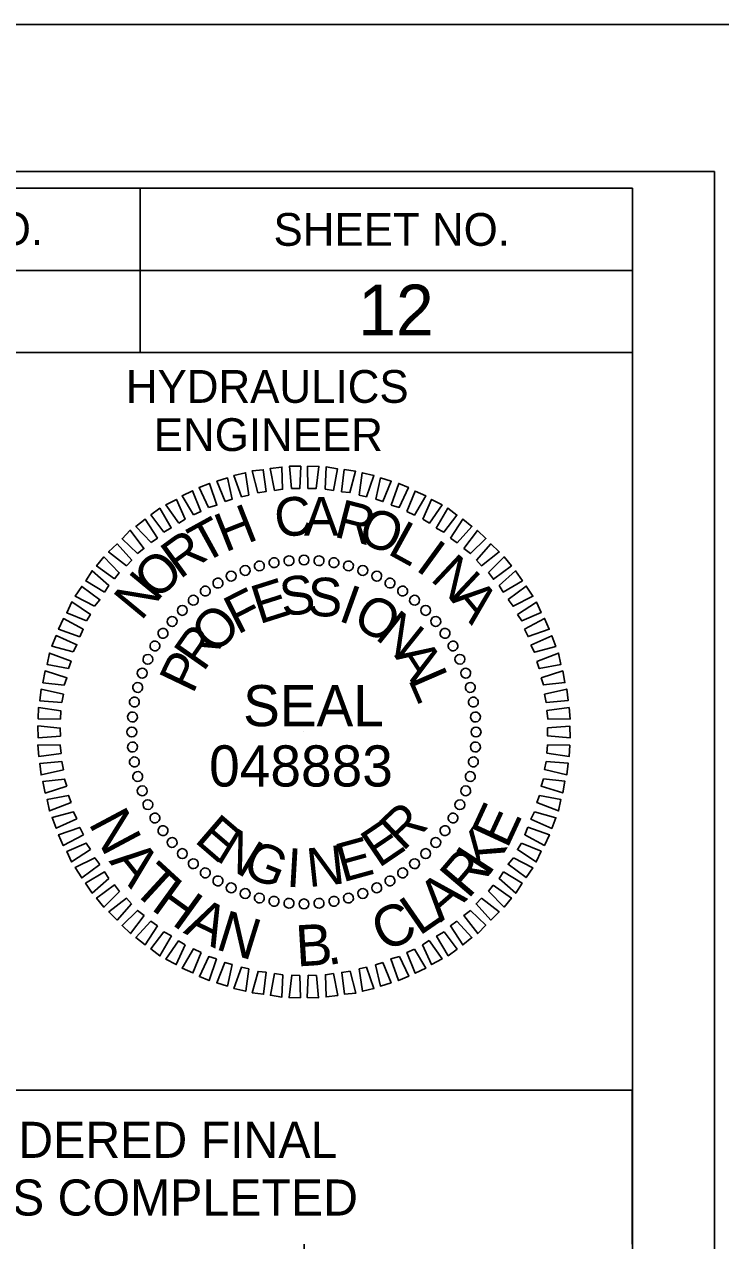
# Model space of a CAD drawing. Extents: x 1650661 to 1652901, y 832691 to 833791.
# Drawn here: x 1652611.6 to 1652717.7, y 833605.5 to 833791 of the extents above; entities that cross this region are included whole.
import ezdxf

# ---------------------------------------------------------------- set-up
doc = ezdxf.new("R2010")
doc.units = 0
for name, color, linetype in [('Default', 7, 'Continuous'), ('Old_Level_2', 7, 'Continuous'), ('Sheet Cutting Line CELL', 7, 'Continuous'), ('Sheet Data Field CELL', 7, 'Continuous'), ('Sheet Plot Border Inside CELL', 7, 'Continuous'), ('Sheet Plot Border Outside CELL', 7, 'Continuous'), ('Sheet Profile CELL', 7, 'Continuous'), ('Sheet Profile Grid Major CELL', 7, 'Continuous'), ('Sheet Sticker Exception Certification CELL', 7, 'Continuous')]:
    doc.layers.add(name, color=color, linetype=linetype)

msp = doc.modelspace()

# ---------------------------------------------------------------- linework, layer by layer
at = {"layer": 'Old_Level_2'}
for p, q in [((1652649.7, 833708.89), (1652649.7, 833708.89)), ((1652651.94, 833709.25), (1652651.94, 833709.25)), ((1652654.24, 833709.34), (1652654.24, 833709.34)), ((1652656.55, 833709.22), (1652656.55, 833709.22)), ((1652658.8, 833708.9), (1652658.8, 833708.9)), ((1652643.15, 833706.9), (1652643.15, 833706.9)), ((1652645.22, 833707.77), (1652645.22, 833707.77)), ((1652647.41, 833708.44), (1652647.41, 833708.44)), ((1652661.01, 833708.46), (1652661.01, 833708.46)), ((1652663.21, 833707.77), (1652663.21, 833707.77)), ((1652665.32, 833706.87), (1652665.32, 833706.87)), ((1652641.13, 833705.82), (1652641.13, 833705.82)), ((1652667.38, 833705.86), (1652667.38, 833705.86)), ((1652637.35, 833703.24), (1652637.35, 833703.24)), ((1652639.16, 833704.58), (1652639.16, 833704.58)), ((1652669.28, 833704.58), (1652669.28, 833704.58)), ((1652671.14, 833703.2), (1652671.14, 833703.2)), ((1652635.66, 833701.64), (1652635.66, 833701.64)), ((1652672.79, 833701.66), (1652672.79, 833701.66)), ((1652634.12, 833699.99), (1652634.12, 833699.99)), ((1652674.38, 833699.96), (1652674.38, 833699.96)), ((1652632.74, 833698.14), (1652632.74, 833698.14)), ((1652675.72, 833698.16), (1652675.72, 833698.16)), ((1652631.46, 833696.23), (1652631.46, 833696.23)), ((1652676.96, 833696.19), (1652676.96, 833696.19)), ((1652630.45, 833694.18), (1652630.45, 833694.18)), ((1652678.04, 833694.17), (1652678.04, 833694.17)), ((1652629.55, 833692.07), (1652629.55, 833692.07)), ((1652678.91, 833692.09), (1652678.91, 833692.09)), ((1652628.85, 833689.86), (1652628.85, 833689.86)), ((1652679.58, 833689.91), (1652679.58, 833689.91)), ((1652628.42, 833687.66), (1652628.42, 833687.66)), ((1652680.04, 833687.62), (1652680.04, 833687.62)), ((1652628.1, 833685.4), (1652628.1, 833685.4)), ((1652680.39, 833685.37), (1652680.39, 833685.37)), ((1652627.98, 833683.1), (1652627.98, 833683.1)), ((1652654.23, 833683.09), (1652654.23, 833683.09)), ((1652680.48, 833683.07), (1652680.48, 833683.07)), ((1652628.07, 833680.8), (1652628.07, 833680.8)), ((1652680.37, 833680.77), (1652680.37, 833680.77)), ((1652628.42, 833678.56), (1652628.42, 833678.56)), ((1652680.04, 833678.52), (1652680.04, 833678.52)), ((1652628.88, 833676.26), (1652628.88, 833676.26)), ((1652679.61, 833676.31), (1652679.61, 833676.31)), ((1652629.55, 833674.08), (1652629.55, 833674.08)), ((1652678.92, 833674.1), (1652678.92, 833674.1)), ((1652630.42, 833672), (1652630.42, 833672)), ((1652678.01, 833672), (1652678.01, 833672)), ((1652631.5, 833669.98), (1652631.5, 833669.98)), ((1652677, 833669.94), (1652677, 833669.94)), ((1652632.74, 833668.02), (1652632.74, 833668.02)), ((1652675.73, 833668.03), (1652675.73, 833668.03)), ((1652634.08, 833666.21), (1652634.08, 833666.21)), ((1652674.35, 833666.18), (1652674.35, 833666.18)), ((1652635.68, 833664.51), (1652635.68, 833664.51)), ((1652672.81, 833664.53), (1652672.81, 833664.53)), ((1652637.32, 833662.97), (1652637.32, 833662.97)), ((1652671.11, 833662.93), (1652671.11, 833662.93)), ((1652639.18, 833661.59), (1652639.18, 833661.59)), ((1652641.08, 833660.32), (1652641.08, 833660.32)), ((1652667.34, 833660.36), (1652667.34, 833660.36)), ((1652669.3, 833661.59), (1652669.3, 833661.59)), ((1652643.14, 833659.31), (1652643.14, 833659.31)), ((1652665.32, 833659.28), (1652665.32, 833659.28)), ((1652645.25, 833658.4), (1652645.25, 833658.4)), ((1652647.46, 833657.71), (1652647.46, 833657.71)), ((1652649.66, 833657.28), (1652649.66, 833657.28)), ((1652651.92, 833656.95), (1652651.92, 833656.95)), ((1652654.22, 833656.83), (1652654.22, 833656.83)), ((1652656.52, 833656.93), (1652656.52, 833656.93)), ((1652658.76, 833657.28), (1652658.76, 833657.28)), ((1652661.05, 833657.74), (1652661.05, 833657.74)), ((1652663.24, 833658.4), (1652663.24, 833658.4))]:
    msp.add_line(p, q, dxfattribs=at)
for points in [[(1652649.72, 833719.93), (1652649.08, 833723.26), (1652650.86, 833723.5), (1652650.97, 833720.11)], [(1652652.33, 833720.24), (1652652.01, 833723.63), (1652653.73, 833723.61), (1652653.58, 833720.21)], [(1652654.84, 833720.23), (1652654.78, 833723.63), (1652656.5, 833723.6), (1652656.09, 833720.2)], [(1652657.45, 833720.12), (1652657.6, 833723.52), (1652659.34, 833723.23), (1652658.71, 833719.93)], [(1652642.22, 833718.23), (1652640.96, 833721.34), (1652642.57, 833721.84), (1652643.31, 833718.61)], [(1652644.71, 833718.95), (1652643.56, 833722.23), (1652645.33, 833722.62), (1652645.81, 833719.23)], [(1652647.21, 833719.57), (1652646.32, 833722.9), (1652648.04, 833723.09), (1652648.47, 833719.75)], [(1652659.97, 833719.74), (1652660.38, 833723.1), (1652662.11, 833722.86), (1652661.23, 833719.61)], [(1652662.65, 833719.21), (1652663.11, 833722.62), (1652664.9, 833722.23), (1652663.75, 833718.97)], [(1652665.17, 833718.58), (1652665.9, 833721.83), (1652667.53, 833721.34), (1652666.27, 833718.23)], [(1652637.39, 833716.21), (1652635.66, 833719.11), (1652637.27, 833719.87), (1652638.53, 833716.7)], [(1652639.67, 833717.35), (1652638.26, 833720.36), (1652639.82, 833721.01), (1652640.97, 833717.68)], [(1652667.54, 833717.68), (1652668.68, 833720.99), (1652670.16, 833720.39), (1652668.75, 833717.33)], [(1652669.91, 833716.72), (1652671.16, 833719.83), (1652672.79, 833719.13), (1652671.07, 833716.17)], [(1652635.16, 833714.92), (1652633.18, 833717.71), (1652634.79, 833718.57), (1652636.15, 833715.56)], [(1652672.33, 833715.56), (1652673.69, 833718.57), (1652675.28, 833717.71), (1652673.34, 833714.95)], [(1652632.89, 833713.57), (1652630.9, 833716.2), (1652632.25, 833717.22), (1652634.02, 833714.22)], [(1652674.4, 833714.19), (1652676.17, 833717.25), (1652677.55, 833716.18), (1652675.56, 833713.58)], [(1652630.93, 833711.97), (1652628.63, 833714.44), (1652630.03, 833715.56), (1652631.91, 833712.66)], [(1652676.57, 833712.66), (1652678.45, 833715.57), (1652679.83, 833714.44), (1652677.57, 833711.94)], [(1652628.86, 833710.31), (1652626.52, 833712.57), (1652627.76, 833713.85), (1652629.84, 833711.06)], [(1652678.58, 833711.07), (1652680.68, 833713.83), (1652681.96, 833712.59), (1652679.59, 833710.3)], [(1652627.17, 833708.45), (1652624.47, 833710.55), (1652625.75, 833711.77), (1652627.99, 833709.3)], [(1652680.5, 833709.27), (1652682.7, 833711.77), (1652683.98, 833710.54), (1652681.3, 833708.45)], [(1652625.37, 833706.43), (1652622.62, 833708.42), (1652623.75, 833709.8), (1652626.09, 833707.38)], [(1652682.36, 833707.42), (1652684.72, 833709.82), (1652685.85, 833708.43), (1652683.11, 833706.39)], [(1652623.84, 833704.42), (1652620.99, 833706.14), (1652621.95, 833707.68), (1652624.5, 833705.42)], [(1652683.96, 833705.41), (1652686.49, 833707.65), (1652687.51, 833706.15), (1652684.61, 833704.43)], [(1652622.31, 833702.3), (1652619.35, 833703.81), (1652620.37, 833705.3), (1652623.13, 833703.25)], [(1652685.36, 833703.29), (1652688.1, 833705.33), (1652689.12, 833703.78), (1652686.11, 833702.26)], [(1652621.09, 833700.03), (1652618.09, 833701.28), (1652618.85, 833702.92), (1652621.7, 833701.03)], [(1652686.76, 833701.02), (1652689.66, 833702.9), (1652690.36, 833701.29), (1652687.41, 833700.03)], [(1652620.09, 833697.6), (1652616.83, 833698.75), (1652617.58, 833700.38), (1652620.59, 833698.76)], [(1652687.85, 833698.79), (1652690.9, 833700.41), (1652691.61, 833698.75), (1652688.39, 833697.65)], [(1652619.08, 833695.29), (1652615.83, 833696.17), (1652616.48, 833697.8), (1652619.64, 833696.39)], [(1652688.83, 833696.35), (1652691.99, 833697.76), (1652692.6, 833696.15), (1652689.37, 833695.26)], [(1652618.34, 833692.76), (1652615.09, 833693.39), (1652615.43, 833695.12), (1652618.74, 833693.87)], [(1652689.71, 833693.85), (1652693.03, 833695.11), (1652693.38, 833693.39), (1652690.09, 833692.76)], [(1652617.71, 833690.24), (1652614.46, 833690.6), (1652614.79, 833692.39), (1652618.11, 833691.35)], [(1652690.38, 833691.35), (1652693.66, 833692.4), (1652694, 833690.63), (1652690.71, 833690.26)], [(1652617.34, 833687.57), (1652613.99, 833687.82), (1652614.16, 833689.6), (1652617.58, 833688.83)], [(1652690.89, 833688.85), (1652694.28, 833689.64), (1652694.47, 833687.87), (1652691.13, 833687.6)], [(1652617.12, 833685.05), (1652613.72, 833685.1), (1652613.79, 833686.83), (1652617.2, 833686.31)], [(1652691.25, 833686.35), (1652694.64, 833686.82), (1652694.78, 833685.05), (1652691.38, 833685.09)], [(1652617.11, 833682.44), (1652613.72, 833682.22), (1652613.69, 833684), (1652617.09, 833683.69)], [(1652691.35, 833683.73), (1652694.75, 833683.95), (1652694.78, 833682.17), (1652691.37, 833682.48)], [(1652617.21, 833679.83), (1652613.82, 833679.35), (1652613.68, 833681.12), (1652617.08, 833681.08)], [(1652691.34, 833681.12), (1652694.74, 833681.07), (1652694.67, 833679.35), (1652691.26, 833679.86)], [(1652617.57, 833677.32), (1652614.18, 833676.53), (1652613.99, 833678.3), (1652617.34, 833678.57)], [(1652691.13, 833678.61), (1652694.48, 833678.35), (1652694.3, 833676.57), (1652690.89, 833677.35)], [(1652618.08, 833674.82), (1652614.81, 833673.77), (1652614.46, 833675.54), (1652617.75, 833675.91)], [(1652690.75, 833675.93), (1652694, 833675.57), (1652693.67, 833673.79), (1652690.36, 833674.83)], [(1652618.75, 833672.32), (1652615.43, 833671.06), (1652615.08, 833672.78), (1652618.37, 833673.41)], [(1652690.12, 833673.41), (1652693.37, 833672.79), (1652693.04, 833671.06), (1652689.72, 833672.31)], [(1652619.63, 833669.83), (1652616.47, 833668.41), (1652615.86, 833670.02), (1652619.09, 833670.92)], [(1652689.38, 833670.89), (1652692.64, 833670), (1652691.98, 833668.37), (1652688.82, 833669.78)], [(1652620.62, 833667.39), (1652617.56, 833665.76), (1652616.85, 833667.42), (1652620.07, 833668.53)], [(1652688.37, 833668.57), (1652691.64, 833667.42), (1652690.88, 833665.79), (1652687.87, 833667.41)], [(1652621.7, 833665.16), (1652618.81, 833663.28), (1652618.1, 833664.88), (1652621.06, 833666.14)], [(1652687.37, 833666.15), (1652690.37, 833664.89), (1652689.62, 833663.26), (1652686.76, 833665.14)], [(1652623.1, 833662.88), (1652620.37, 833660.84), (1652619.34, 833662.4), (1652622.35, 833663.91)], [(1652686.15, 833663.88), (1652689.11, 833662.36), (1652688.09, 833660.88), (1652685.33, 833662.92)], [(1652624.5, 833660.76), (1652621.97, 833658.52), (1652620.96, 833660.02), (1652623.85, 833661.74)], [(1652684.62, 833661.76), (1652687.48, 833660.03), (1652686.51, 833658.5), (1652683.96, 833660.75)], [(1652626.1, 833658.75), (1652623.74, 833656.35), (1652622.62, 833657.75), (1652625.35, 833659.78)], [(1652683.09, 833659.74), (1652685.84, 833657.75), (1652684.72, 833656.37), (1652682.37, 833658.79)], [(1652627.97, 833656.9), (1652625.76, 833654.4), (1652624.48, 833655.63), (1652627.17, 833657.72)], [(1652681.29, 833657.72), (1652684, 833655.63), (1652682.71, 833654.4), (1652680.47, 833656.87)], [(1652629.88, 833655.1), (1652627.78, 833652.35), (1652626.51, 833653.58), (1652628.87, 833655.87)], [(1652679.6, 833655.86), (1652681.94, 833653.6), (1652680.71, 833652.33), (1652678.62, 833655.12)], [(1652631.89, 833653.52), (1652630.01, 833650.61), (1652628.63, 833651.73), (1652630.89, 833654.23)], [(1652677.54, 833654.21), (1652679.83, 833651.74), (1652678.44, 833650.61), (1652676.56, 833653.51)], [(1652634.06, 833651.98), (1652632.29, 833648.92), (1652630.91, 833649.99), (1652632.9, 833652.59)], [(1652636.13, 833650.61), (1652634.77, 833647.6), (1652633.18, 833648.46), (1652635.12, 833651.22)], [(1652673.3, 833651.26), (1652675.28, 833648.47), (1652673.68, 833647.6), (1652672.32, 833650.61)], [(1652675.58, 833652.6), (1652677.56, 833649.97), (1652676.22, 833648.95), (1652674.44, 833651.96)], [(1652638.55, 833649.45), (1652637.3, 833646.34), (1652635.67, 833647.04), (1652637.39, 833650)], [(1652671.07, 833649.96), (1652672.8, 833647.06), (1652671.19, 833646.3), (1652669.93, 833649.47)], [(1652640.92, 833648.5), (1652639.78, 833645.18), (1652638.3, 833645.78), (1652639.72, 833648.84)], [(1652643.29, 833647.6), (1652642.57, 833644.34), (1652640.94, 833644.83), (1652642.19, 833647.94)], [(1652666.25, 833647.94), (1652667.5, 833644.83), (1652665.89, 833644.33), (1652665.15, 833647.56)], [(1652668.79, 833648.82), (1652670.2, 833645.82), (1652668.65, 833645.16), (1652667.49, 833648.49)], [(1652645.81, 833646.96), (1652645.35, 833643.55), (1652643.57, 833643.94), (1652644.71, 833647.2)], [(1652648.49, 833646.43), (1652648.08, 833643.08), (1652646.35, 833643.31), (1652647.23, 833646.57)], [(1652651.01, 833646.06), (1652650.86, 833642.65), (1652649.13, 833642.94), (1652649.75, 833646.24)], [(1652653.62, 833645.95), (1652653.68, 833642.55), (1652651.96, 833642.57), (1652652.37, 833645.98)], [(1652656.13, 833645.94), (1652656.46, 833642.54), (1652654.73, 833642.57), (1652654.88, 833645.97)], [(1652658.74, 833646.24), (1652659.38, 833642.91), (1652657.6, 833642.67), (1652657.49, 833646.07)], [(1652661.25, 833646.6), (1652662.14, 833643.27), (1652660.42, 833643.08), (1652660, 833646.42)], [(1652663.75, 833647.22), (1652664.9, 833643.95), (1652663.13, 833643.55), (1652662.65, 833646.94)]]:
    msp.add_lwpolyline(points, close=True, dxfattribs=at)
for centre, major_axis in [((1652645.26, 833707.73), (-0.258, 0.708)), ((1652647.44, 833708.42), (-0.195, 0.727)), ((1652649.68, 833708.92), (-0.131, 0.742)), ((1652651.95, 833709.21), (-0.066, 0.75)), ((1652654.23, 833709.31), (0, 0.753)), ((1652656.52, 833709.21), (0.066, 0.75)), ((1652658.79, 833708.92), (0.131, 0.742)), ((1652661.02, 833708.42), (0.195, 0.727)), ((1652663.2, 833707.73), (0.258, 0.708)), ((1652643.15, 833706.86), (-0.318, 0.682)), ((1652665.32, 833706.86), (0.318, 0.682)), ((1652639.19, 833704.57), (-0.432, 0.617)), ((1652641.12, 833705.8), (-0.376, 0.652)), ((1652667.35, 833705.8), (0.376, 0.652)), ((1652669.27, 833704.57), (0.432, 0.617)), ((1652637.37, 833703.18), (-0.484, 0.577)), ((1652671.09, 833703.18), (0.484, 0.577)), ((1652635.69, 833701.63), (-0.532, 0.532)), ((1652672.78, 833701.63), (0.532, 0.532)), ((1652634.14, 833699.95), (-0.577, 0.484)), ((1652674.32, 833699.95), (0.577, 0.484)), ((1652632.75, 833698.13), (-0.617, 0.432)), ((1652675.72, 833698.13), (0.617, 0.432)), ((1652631.52, 833696.2), (-0.652, 0.376)), ((1652676.95, 833696.2), (0.652, 0.376)), ((1652630.46, 833694.17), (-0.682, 0.318)), ((1652678, 833694.17), (0.682, 0.318)), ((1652629.59, 833692.06), (-0.708, 0.258)), ((1652678.88, 833692.06), (0.708, 0.258)), ((1652628.9, 833689.87), (-0.727, 0.195)), ((1652679.57, 833689.87), (0.727, 0.195)), ((1652628.4, 833687.64), (-0.742, 0.131)), ((1652680.06, 833687.64), (0.742, 0.131)), ((1652628.1, 833685.37), (-0.75, 0.066)), ((1652680.36, 833685.37), (0.75, 0.066)), ((1652628, 833683.09), (-0.753, 0)), ((1652680.46, 833683.09), (0.753, 0)), ((1652628.1, 833680.8), (-0.75, -0.066)), ((1652680.36, 833680.8), (0.75, -0.066)), ((1652628.4, 833678.53), (-0.742, -0.131)), ((1652680.06, 833678.53), (0.742, -0.131)), ((1652628.9, 833676.3), (-0.727, -0.195)), ((1652679.57, 833676.3), (0.727, -0.195)), ((1652629.59, 833674.12), (-0.708, -0.258)), ((1652678.88, 833674.12), (0.708, -0.258)), ((1652630.46, 833672), (-0.682, -0.318)), ((1652678, 833672), (0.682, -0.318)), ((1652631.52, 833669.97), (-0.652, -0.376)), ((1652676.95, 833669.97), (0.652, -0.376)), ((1652632.75, 833668.04), (-0.617, -0.432)), ((1652675.72, 833668.04), (0.617, -0.432)), ((1652634.14, 833666.23), (-0.577, -0.484)), ((1652674.32, 833666.23), (0.577, -0.484)), ((1652635.69, 833664.54), (-0.532, -0.532)), ((1652672.78, 833664.54), (0.532, -0.532)), ((1652637.37, 833662.99), (-0.484, -0.577)), ((1652639.19, 833661.6), (-0.432, -0.617)), ((1652669.27, 833661.6), (0.432, -0.617)), ((1652671.09, 833662.99), (0.484, -0.577)), ((1652641.12, 833660.37), (-0.376, -0.652)), ((1652667.35, 833660.37), (0.376, -0.652)), ((1652643.15, 833659.32), (-0.318, -0.682)), ((1652645.26, 833658.44), (-0.258, -0.708)), ((1652647.44, 833657.75), (-0.195, -0.727)), ((1652661.02, 833657.75), (0.195, -0.727)), ((1652663.2, 833658.44), (0.258, -0.708)), ((1652665.32, 833659.32), (0.318, -0.682)), ((1652649.68, 833657.26), (-0.131, -0.742)), ((1652651.95, 833656.96), (-0.066, -0.75)), ((1652654.23, 833656.86), (0, -0.753)), ((1652656.52, 833656.96), (0.066, -0.75)), ((1652658.79, 833657.26), (0.131, -0.742))]:
    msp.add_ellipse(centre, major_axis=major_axis, ratio=0.999708, dxfattribs=at)
at = {"layer": 'Sheet Cutting Line CELL'}
msp.add_line((1652721.28, 833791.02), (1651037.28, 833791.02), dxfattribs=at)
at = {"layer": 'Sheet Plot Border Inside CELL'}
msp.add_lwpolyline([(1651050.28, 832713.47), (1652716.78, 832713.47), (1652716.78, 833768.57), (1651050.28, 833768.57)], close=True, dxfattribs=at)
at = {"layer": 'Sheet Plot Border Outside CELL'}
msp.add_lwpolyline([(1651037.28, 832691.02), (1652721.28, 832691.02), (1652721.28, 833791.02), (1651037.28, 833791.02)], close=True, dxfattribs=at)
at = {"layer": 'Sheet Profile CELL'}
for p, q in [((1652629.28, 833765.97), (1652629.28, 833740.97)), ((1652504.23, 833753.47), (1652704.28, 833753.47))]:
    msp.add_line(p, q, dxfattribs=at)
for points in [[(1652704.28, 833766.02), (1651204.28, 833766.02), (1651204.28, 832716.02), (1652704.28, 832716.02)], [(1652504.23, 833766.02), (1652704.28, 833766.02), (1652704.28, 833740.97), (1652504.23, 833740.97)], [(1652604.28, 833740.97), (1652704.28, 833740.97), (1652704.28, 833628.47), (1652604.28, 833628.47)]]:
    msp.add_lwpolyline(points, close=True, dxfattribs=at)
at = {"layer": 'Sheet Profile Grid Major CELL'}
msp.add_lwpolyline([(1652654.28, 833604.97), (1652654.28, 833266.02), (1652704.28, 833266.02), (1652704.28, 833616.02)], dxfattribs=at)
at = {"layer": 'Sheet Sticker Exception Certification CELL'}
for p, q in [((1652504.23, 833628.47), (1652704.27, 833628.47)), ((1652504.23, 833628.47), (1652704.27, 833628.47)), ((1652704.27, 833628.46), (1652704.27, 833604.96)), ((1652704.27, 833628.46), (1652704.27, 833604.96))]:
    msp.add_line(p, q, dxfattribs=at)

# ---------------------------------------------------------------- texts
at = {"layer": 'Default'}
for s, rotation, p in [('N', 298.0773, (1652621.31, 833669.19)), ('E', 65.2198, (1652685.2, 833665.13)), ('K', 57.024, (1652682.33, 833660.9)), ('A', 308.6891, (1652624.42, 833663.36)), ('R', 49.6233, (1652679.25, 833657.47)), ('T', 317.4354, (1652627.76, 833659.05)), ('H', 324.1633, (1652630.75, 833656.11)), ('A', 40.877, (1652675.07, 833653.97)), ('A', 334.0411, (1652635.72, 833652.48)), ('C', 25.1886, (1652666.43, 833649.42)), ('L', 34.6689, (1652671.8, 833651.89)), ('N', 342.7874, (1652640.58, 833650.01)), ('B', 3.4911, (1652653.14, 833647.31)), ('.', 11.1059, (1652657.89, 833647.47))]:
    msp.add_text(s, height=6.27, rotation=rotation, dxfattribs=at).set_placement(p)
at = {"layer": 'Old_Level_2'}
for s, rotation, p in [('C', 7.2199, (1652650.11, 833712.67)), ('A', 0.0203, (1652654.23, 833713.05)), ('R', 345.6211, (1652658.63, 833712.92)), ('T', 28.8198, (1652638.83, 833708.65)), ('H', 21.6195, (1652642.2, 833710.44)), ('O', 338.4212, (1652662.14, 833712.2)), ('L', 331.2209, (1652666.78, 833710.34)), ('R', 36.0205, (1652635.31, 833706.29)), ('I', 324.0201, (1652671.06, 833707.91)), ('O', 43.2217, (1652631.76, 833702.99)), ('N', 316.8189, (1652673.33, 833706.33)), ('N', 50.4235, (1652629.41, 833699.91)), ('S', 8.2556, (1652651, 833700.65)), ('S', 358.9004, (1652654.76, 833700.77)), ('F', 26.967, (1652644.09, 833697.87)), ('E', 17.6111, (1652647.41, 833699.49)), ('I', 340.1896, (1652659.27, 833700.12)), ('A', 309.6172, (1652676.47, 833703.29)), ('O', 330.8335, (1652661.37, 833699.42)), ('O', 45.6812, (1652640.69, 833694.72)), ('N', 321.4766, (1652664.91, 833697.39)), ('R', 55.0397, (1652638.91, 833692.13)), ('A', 302.7603, (1652667.94, 833694.73)), ('P', 64.3989, (1652637.29, 833688.75)), ('L', 293.4009, (1652670.04, 833691.15)), ('R', 43.4814, (1652669.3, 833664.78)), ('E', 319.2769, (1652637.37, 833666.42)), ('E', 34.1241, (1652665.63, 833662.26)), ('N', 328.634, (1652640.56, 833663.65)), ('G', 337.9902, (1652644.57, 833661.37)), ('E', 15.4118, (1652660.12, 833660.13)), ('I', 356.7012, (1652651.45, 833659.5)), ('N', 6.0564, (1652654.96, 833659.41))]:
    msp.add_text(s, height=5.9, rotation=rotation, dxfattribs=at).set_placement(p)
for s, height, p in [('SEAL', 6.273, (1652644.96, 833683.97)), ('048883', 6.275, (1652639.78, 833674.77))]:
    msp.add_text(s, height=height, dxfattribs=at).set_placement(p)
at = {"layer": 'Sheet Data Field CELL'}
msp.add_text('12', height=7.75, dxfattribs=at).set_placement((1652662.49, 833743.57))
at = {"layer": 'Sheet Profile CELL'}
for s, height, p in [('PROJECT REFERENCE NO.', 5.0001, (1652526.44, 833757.34)), ('SHEET NO.', 5, (1652649.59, 833757.24)), ('HYDRAULICS', 5, (1652627.09, 833733.29)), ('ENGINEER', 5, (1652631.34, 833725.94))]:
    msp.add_text(s, height=height, dxfattribs=at).set_placement(p)
at = {"layer": 'Sheet Sticker Exception Certification CELL'}
for s, p in [('DOCUMENT NOT CONSIDERED FINAL', (1652525.3, 833618.13)), ('DOCUMENT NOT CONSIDERED FINAL', (1652525.3, 833618.13)), ('UNLESS ALL SIGNATURES COMPLETED', (1652520.23, 833609.33)), ('UNLESS ALL SIGNATURES COMPLETED', (1652520.23, 833609.33))]:
    msp.add_text(s, height=5.5, dxfattribs=at).set_placement(p)

doc.saveas('drawing.dxf')
